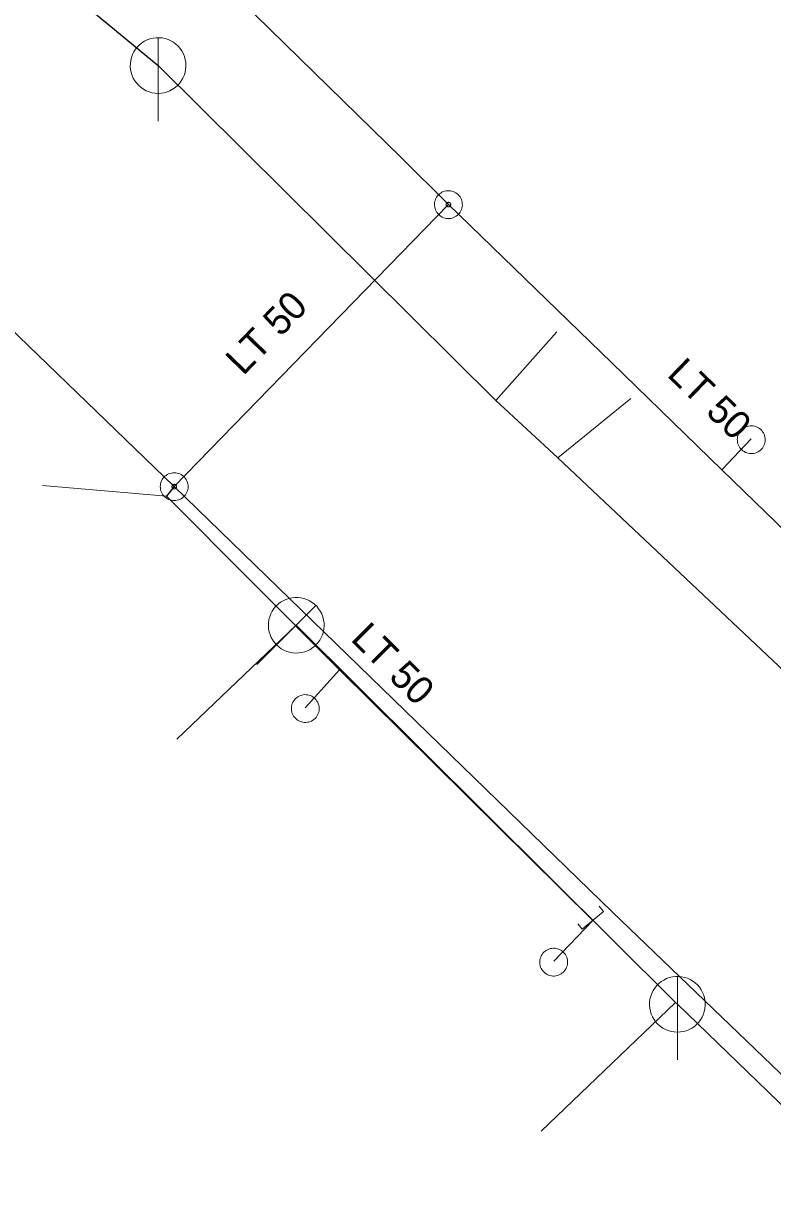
# Model space of a CAD drawing. Extents: x -807203 to -805207, y -993656 to -992505.
# Drawn here: x -805985.68 to -805958.79, y -993323.34 to -993281.18 of the extents above; entities that cross this region are included whole.
import ezdxf

# ---------------------------------------------------------------- set-up
doc = ezdxf.new("R2010")
doc.units = 0
doc.header["$LTSCALE"] = 0.4
for name, color, linetype, lineweight in [('1', 7, 'Continuous', 13), ('11', 7, 'Continuous', 13), ('13', 7, 'Continuous', 13), ('14', 7, 'Continuous', 25), ('17', 7, 'Continuous', 25), ('22', 7, 'Continuous', 13), ('23', 7, 'Continuous', 13), ('47', 7, 'Continuous', 13)]:
    doc.layers.add(name, color=color, linetype=linetype, lineweight=lineweight)

msp = doc.modelspace()

# ---------------------------------------------------------------- linework, layer by layer
at = {"layer": '11'}
for p, q in [((-805966.54, -993292.252), (-805968.73, -993294.715)), ((-805963.884, -993294.643), (-805966.495, -993296.778)), ((-805980.176, -993306.88), (-805975.89, -993302.789)), ((-805967.097, -993320.95), (-805962.28, -993316.329)), ((-805962.21, -993316.399), (-805947.879, -993330.26))]:
    msp.add_line(p, q, dxfattribs=at)
msp.add_lwpolyline([(-805975.89, -993302.789), (-805962.28, -993316.329), (-805962.21, -993316.399)], dxfattribs=at)
at = {"layer": '13'}
for p, q in [((-805960.618, -993297.208), (-805959.558, -993296.094)), ((-805980.55, -993298.156), (-805985.005, -993297.765)), ((-805974.333, -993304.386), (-805975.566, -993305.748)), ((-805965.239, -993313.388), (-805966.649, -993314.853))]:
    msp.add_line(p, q, dxfattribs=at)
at = {"layer": '14'}
for points in [[(-806015.82, -993248.39), (-806008.844, -993255.179), (-805995.221, -993268.897), (-805983.297, -993280.672), (-805980.85, -993282.69)], [(-805980.85, -993282.69), (-805968.73, -993294.715), (-805966.495, -993296.778), (-805953.969, -993308.596), (-805943.489, -993317.82)]]:
    msp.add_lwpolyline(points, dxfattribs=at)
at = {"layer": '17'}
msp.add_line((-805970.428, -993287.685), (-805980.27, -993297.811), dxfattribs=at)
for points in [[(-805970.428, -993287.685), (-805972.109, -993286.008), (-805978.403, -993279.84), (-805988.86, -993269.541), (-805996.668, -993261.975), (-806000.375, -993258.351), (-806005.914, -993252.87), (-806019.053, -993241.45)], [(-805980.27, -993297.811), (-805996.344, -993282.298), (-806025.237, -993255.101)], [(-805970.428, -993287.685), (-805964.557, -993293.37), (-805960.618, -993297.208), (-805957.092, -993300.616), (-805952.748, -993305.003)], [(-805980.27, -993297.811), (-805980.55, -993298.156), (-805974.333, -993304.386), (-805965.239, -993313.388)], [(-805980.27, -993297.811), (-805964.539, -993313.096), (-805944.059, -993332.754), (-805925.796, -993349.072), (-805905.688, -993366.883), (-805894.556, -993375.978), (-805881.298, -993386.71), (-805877.651, -993389.561), (-805871.269, -993394.798), (-805850.666, -993411.467), (-805839.3, -993421.037), (-805830.275, -993428.564)]]:
    msp.add_lwpolyline(points, dxfattribs=at)
at = {"layer": '22'}
for p, q in [((-805980.85, -993284.69), (-805980.849, -993281.69)), ((-805977.306, -993304.201), (-805975.182, -993302.083)), ((-805962.21, -993318.399), (-805962.209, -993315.399))]:
    msp.add_line(p, q, dxfattribs=at)
for points in [[(-805979.85, -993282.69), (-805979.855, -993282.581), (-805979.873, -993282.473), (-805979.903, -993282.367), (-805979.943, -993282.266), (-805979.995, -993282.169), (-805980.057, -993282.079), (-805980.129, -993281.996), (-805980.209, -993281.922), (-805980.297, -993281.856), (-805980.391, -993281.801), (-805980.491, -993281.756), (-805980.596, -993281.723), (-805980.703, -993281.701), (-805980.812, -993281.691), (-805980.922, -993281.693), (-805981.03, -993281.707), (-805981.137, -993281.732), (-805981.24, -993281.769), (-805981.338, -993281.818), (-805981.43, -993281.876), (-805981.516, -993281.945), (-805981.593, -993282.022), (-805981.662, -993282.108), (-805981.721, -993282.2), (-805981.769, -993282.298), (-805981.806, -993282.401), (-805981.832, -993282.508), (-805981.846, -993282.616), (-805981.849, -993282.726), (-805981.839, -993282.835), (-805981.818, -993282.942), (-805981.784, -993283.046), (-805981.74, -993283.146), (-805981.685, -993283.241), (-805981.619, -993283.329), (-805981.545, -993283.409), (-805981.462, -993283.481), (-805981.372, -993283.543), (-805981.276, -993283.595), (-805981.174, -993283.636), (-805981.069, -993283.666), (-805980.961, -993283.684), (-805980.851, -993283.69), (-805980.742, -993283.684), (-805980.634, -993283.666), (-805980.529, -993283.637), (-805980.427, -993283.596), (-805980.33, -993283.544), (-805980.24, -993283.482), (-805980.157, -993283.411), (-805980.082, -993283.331), (-805980.017, -993283.243), (-805979.961, -993283.149), (-805979.917, -993283.049), (-805979.883, -993282.945), (-805979.861, -993282.837), (-805979.851, -993282.728)], [(-805975.184, -993303.497), (-805975.111, -993303.416), (-805975.047, -993303.327), (-805974.993, -993303.23), (-805974.95, -993303.131), (-805974.918, -993303.025), (-805974.898, -993302.918), (-805974.89, -993302.808), (-805974.894, -993302.7), (-805974.91, -993302.591), (-805974.937, -993302.485), (-805974.976, -993302.383), (-805975.027, -993302.285), (-805975.087, -993302.194), (-805975.156, -993302.109), (-805975.236, -993302.033), (-805975.322, -993301.966), (-805975.415, -993301.908), (-805975.514, -993301.862), (-805975.618, -993301.827), (-805975.724, -993301.803), (-805975.833, -993301.79), (-805975.942, -993301.79), (-805976.052, -993301.802), (-805976.159, -993301.825), (-805976.262, -993301.861), (-805976.361, -993301.907), (-805976.455, -993301.964), (-805976.542, -993302.031), (-805976.621, -993302.107), (-805976.691, -993302.191), (-805976.752, -993302.282), (-805976.802, -993302.379), (-805976.841, -993302.481), (-805976.87, -993302.587), (-805976.885, -993302.696), (-805976.89, -993302.805), (-805976.882, -993302.914), (-805976.862, -993303.022), (-805976.831, -993303.126), (-805976.788, -993303.228), (-805976.735, -993303.323), (-805976.672, -993303.412), (-805976.599, -993303.494), (-805976.517, -993303.567), (-805976.428, -993303.631), (-805976.334, -993303.685), (-805976.233, -993303.728), (-805976.127, -993303.76), (-805976.02, -993303.78), (-805975.911, -993303.789), (-805975.801, -993303.785), (-805975.693, -993303.769), (-805975.587, -993303.742), (-805975.485, -993303.703), (-805975.387, -993303.654), (-805975.295, -993303.593), (-805975.211, -993303.523)], [(-805961.21, -993316.399), (-805961.215, -993316.29), (-805961.233, -993316.182), (-805961.263, -993316.076), (-805961.303, -993315.975), (-805961.355, -993315.878), (-805961.417, -993315.788), (-805961.489, -993315.705), (-805961.569, -993315.631), (-805961.657, -993315.565), (-805961.751, -993315.51), (-805961.851, -993315.465), (-805961.956, -993315.432), (-805962.063, -993315.41), (-805962.172, -993315.4), (-805962.282, -993315.402), (-805962.39, -993315.416), (-805962.497, -993315.441), (-805962.6, -993315.478), (-805962.698, -993315.527), (-805962.79, -993315.585), (-805962.876, -993315.654), (-805962.953, -993315.731), (-805963.022, -993315.817), (-805963.081, -993315.909), (-805963.129, -993316.007), (-805963.166, -993316.11), (-805963.192, -993316.217), (-805963.206, -993316.325), (-805963.209, -993316.435), (-805963.199, -993316.544), (-805963.178, -993316.651), (-805963.144, -993316.755), (-805963.1, -993316.855), (-805963.045, -993316.95), (-805962.979, -993317.038), (-805962.905, -993317.118), (-805962.822, -993317.19), (-805962.732, -993317.252), (-805962.636, -993317.304), (-805962.534, -993317.345), (-805962.429, -993317.375), (-805962.321, -993317.393), (-805962.211, -993317.399), (-805962.102, -993317.393), (-805961.994, -993317.375), (-805961.889, -993317.346), (-805961.787, -993317.305), (-805961.69, -993317.253), (-805961.6, -993317.191), (-805961.517, -993317.12), (-805961.442, -993317.04), (-805961.377, -993316.952), (-805961.321, -993316.858), (-805961.277, -993316.758), (-805961.243, -993316.654), (-805961.221, -993316.546), (-805961.211, -993316.437)]]:
    msp.add_lwpolyline(points, close=True, dxfattribs=at)
at = {"layer": '23'}
for points in [[(-805959.216, -993295.76), (-805959.256, -993295.726), (-805959.3, -993295.696), (-805959.346, -993295.673), (-805959.395, -993295.653), (-805959.445, -993295.639), (-805959.497, -993295.63), (-805959.549, -993295.627), (-805959.601, -993295.629), (-805959.653, -993295.636), (-805959.703, -993295.648), (-805959.753, -993295.666), (-805959.801, -993295.69), (-805959.844, -993295.717), (-805959.885, -993295.749), (-805959.923, -993295.785), (-805959.957, -993295.827), (-805959.986, -993295.868), (-805960.011, -993295.916), (-805960.03, -993295.963), (-805960.045, -993296.013), (-805960.053, -993296.067), (-805960.057, -993296.118), (-805960.055, -993296.171), (-805960.048, -993296.223), (-805960.035, -993296.273), (-805960.016, -993296.322), (-805959.994, -993296.369), (-805959.966, -993296.413), (-805959.933, -993296.454), (-805959.897, -993296.492), (-805959.858, -993296.526), (-805959.814, -993296.555), (-805959.767, -993296.58), (-805959.719, -993296.599), (-805959.669, -993296.612), (-805959.618, -993296.622), (-805959.565, -993296.626), (-805959.512, -993296.624), (-805959.461, -993296.616)], [(-805960.011, -993295.916), (-805960.03, -993295.963), (-805960.045, -993296.013), (-805960.053, -993296.067), (-805960.057, -993296.118), (-805960.055, -993296.171), (-805960.048, -993296.223), (-805960.035, -993296.273), (-805960.016, -993296.322), (-805959.994, -993296.369), (-805959.966, -993296.413), (-805959.933, -993296.454), (-805959.897, -993296.492), (-805959.858, -993296.526), (-805959.814, -993296.555), (-805959.767, -993296.58), (-805959.719, -993296.599), (-805959.669, -993296.612), (-805959.618, -993296.622), (-805959.565, -993296.626), (-805959.512, -993296.624), (-805959.461, -993296.616), (-805959.411, -993296.604), (-805959.361, -993296.586), (-805959.314, -993296.564), (-805959.27, -993296.534), (-805959.229, -993296.502), (-805959.191, -993296.467), (-805959.158, -993296.426), (-805959.128, -993296.383), (-805959.103, -993296.336), (-805959.085, -993296.288), (-805959.07, -993296.237), (-805959.06, -993296.187), (-805959.058, -993296.134), (-805959.059, -993296.082), (-805959.066, -993296.031), (-805959.079, -993295.979), (-805959.097, -993295.93), (-805959.12, -993295.883)], [(-805959.461, -993296.616), (-805959.411, -993296.604), (-805959.361, -993296.586), (-805959.314, -993296.564), (-805959.27, -993296.534), (-805959.229, -993296.502), (-805959.191, -993296.467), (-805959.158, -993296.426), (-805959.128, -993296.383), (-805959.103, -993296.336), (-805959.085, -993296.288), (-805959.07, -993296.237), (-805959.06, -993296.187), (-805959.058, -993296.134), (-805959.059, -993296.082), (-805959.066, -993296.031), (-805959.079, -993295.979), (-805959.097, -993295.93), (-805959.12, -993295.883), (-805959.149, -993295.839), (-805959.18, -993295.798), (-805959.216, -993295.76), (-805959.256, -993295.726), (-805959.3, -993295.696), (-805959.346, -993295.673), (-805959.395, -993295.653), (-805959.445, -993295.639), (-805959.497, -993295.63), (-805959.549, -993295.627), (-805959.601, -993295.629), (-805959.653, -993295.636), (-805959.703, -993295.648), (-805959.753, -993295.666), (-805959.801, -993295.69), (-805959.844, -993295.717), (-805959.885, -993295.749), (-805959.923, -993295.785), (-805959.957, -993295.827), (-805959.986, -993295.868), (-805960.011, -993295.916)], [(-805959.12, -993295.883), (-805959.149, -993295.839), (-805959.18, -993295.798), (-805959.216, -993295.76)], [(-805975.21, -993305.429), (-805975.249, -993305.393), (-805975.291, -993305.362), (-805975.336, -993305.337), (-805975.384, -993305.315), (-805975.433, -993305.298), (-805975.485, -993305.288), (-805975.536, -993305.282), (-805975.588, -993305.281), (-805975.64, -993305.286), (-805975.692, -993305.296), (-805975.742, -993305.312), (-805975.791, -993305.333), (-805975.836, -993305.359), (-805975.877, -993305.389), (-805975.917, -993305.423), (-805975.953, -993305.463), (-805975.983, -993305.504), (-805976.01, -993305.55), (-805976.032, -993305.596), (-805976.049, -993305.646), (-805976.059, -993305.699), (-805976.065, -993305.75), (-805976.066, -993305.803), (-805976.062, -993305.855), (-805976.051, -993305.905), (-805976.034, -993305.956), (-805976.014, -993306.003), (-805975.988, -993306.049), (-805975.956, -993306.091), (-805975.923, -993306.131), (-805975.884, -993306.166), (-805975.842, -993306.197), (-805975.796, -993306.224), (-805975.749, -993306.246), (-805975.7, -993306.261), (-805975.649, -993306.272), (-805975.597, -993306.279), (-805975.544, -993306.279), (-805975.492, -993306.274)], [(-805976.01, -993305.55), (-805976.032, -993305.596), (-805976.049, -993305.646), (-805976.059, -993305.699), (-805976.065, -993305.75), (-805976.066, -993305.803), (-805976.062, -993305.855), (-805976.051, -993305.905), (-805976.034, -993305.956), (-805976.014, -993306.003), (-805975.988, -993306.049), (-805975.956, -993306.091), (-805975.923, -993306.131), (-805975.884, -993306.166), (-805975.842, -993306.197), (-805975.796, -993306.224), (-805975.749, -993306.246), (-805975.7, -993306.261), (-805975.649, -993306.272), (-805975.597, -993306.279), (-805975.544, -993306.279), (-805975.492, -993306.274), (-805975.441, -993306.264), (-805975.391, -993306.248), (-805975.343, -993306.228), (-805975.297, -993306.201), (-805975.256, -993306.17), (-805975.216, -993306.136), (-805975.181, -993306.098), (-805975.15, -993306.056), (-805975.123, -993306.01), (-805975.102, -993305.963), (-805975.085, -993305.913), (-805975.073, -993305.863), (-805975.068, -993305.81), (-805975.067, -993305.758), (-805975.072, -993305.706), (-805975.082, -993305.654), (-805975.098, -993305.604), (-805975.119, -993305.556)], [(-805975.492, -993306.274), (-805975.441, -993306.264), (-805975.391, -993306.248), (-805975.343, -993306.228), (-805975.297, -993306.201), (-805975.256, -993306.17), (-805975.216, -993306.136), (-805975.181, -993306.098), (-805975.15, -993306.056), (-805975.123, -993306.01), (-805975.102, -993305.963), (-805975.085, -993305.913), (-805975.073, -993305.863), (-805975.068, -993305.81), (-805975.067, -993305.758), (-805975.072, -993305.706), (-805975.082, -993305.654), (-805975.098, -993305.604), (-805975.119, -993305.556), (-805975.146, -993305.511), (-805975.176, -993305.469), (-805975.21, -993305.429), (-805975.249, -993305.393), (-805975.291, -993305.362), (-805975.336, -993305.337), (-805975.384, -993305.315), (-805975.433, -993305.298), (-805975.485, -993305.288), (-805975.536, -993305.282), (-805975.588, -993305.281), (-805975.64, -993305.286), (-805975.692, -993305.296), (-805975.742, -993305.312), (-805975.791, -993305.333), (-805975.836, -993305.359), (-805975.877, -993305.389), (-805975.917, -993305.423), (-805975.953, -993305.463), (-805975.983, -993305.504), (-805976.01, -993305.55)], [(-805975.119, -993305.556), (-805975.146, -993305.511), (-805975.176, -993305.469), (-805975.21, -993305.429)], [(-805966.293, -993314.534), (-805966.332, -993314.498), (-805966.374, -993314.467), (-805966.419, -993314.442), (-805966.467, -993314.42), (-805966.516, -993314.403), (-805966.568, -993314.393), (-805966.619, -993314.387), (-805966.671, -993314.386), (-805966.723, -993314.391), (-805966.775, -993314.401), (-805966.825, -993314.417), (-805966.874, -993314.438), (-805966.919, -993314.464), (-805966.96, -993314.494), (-805967, -993314.528), (-805967.036, -993314.568), (-805967.066, -993314.609), (-805967.093, -993314.655), (-805967.115, -993314.701), (-805967.132, -993314.751), (-805967.142, -993314.804), (-805967.148, -993314.855), (-805967.149, -993314.908), (-805967.145, -993314.96), (-805967.134, -993315.01), (-805967.117, -993315.061), (-805967.097, -993315.108), (-805967.071, -993315.154), (-805967.039, -993315.196), (-805967.006, -993315.236), (-805966.967, -993315.271), (-805966.925, -993315.302), (-805966.879, -993315.329), (-805966.832, -993315.351), (-805966.783, -993315.366), (-805966.732, -993315.377), (-805966.68, -993315.384), (-805966.627, -993315.384), (-805966.575, -993315.379)], [(-805966.575, -993315.379), (-805966.524, -993315.369), (-805966.474, -993315.353), (-805966.426, -993315.333), (-805966.38, -993315.306), (-805966.339, -993315.275), (-805966.299, -993315.241), (-805966.264, -993315.203), (-805966.233, -993315.161), (-805966.206, -993315.115), (-805966.185, -993315.068), (-805966.168, -993315.018), (-805966.156, -993314.968), (-805966.151, -993314.915), (-805966.15, -993314.863), (-805966.155, -993314.811), (-805966.165, -993314.759), (-805966.181, -993314.709), (-805966.202, -993314.661), (-805966.229, -993314.616), (-805966.259, -993314.574), (-805966.293, -993314.534), (-805966.332, -993314.498), (-805966.374, -993314.467), (-805966.419, -993314.442), (-805966.467, -993314.42), (-805966.516, -993314.403), (-805966.568, -993314.393), (-805966.619, -993314.387), (-805966.671, -993314.386), (-805966.723, -993314.391), (-805966.775, -993314.401), (-805966.825, -993314.417), (-805966.874, -993314.438), (-805966.919, -993314.464), (-805966.96, -993314.494), (-805967, -993314.528), (-805967.036, -993314.568), (-805967.066, -993314.609), (-805967.093, -993314.655)], [(-805967.093, -993314.655), (-805967.115, -993314.701), (-805967.132, -993314.751), (-805967.142, -993314.804), (-805967.148, -993314.855), (-805967.149, -993314.908), (-805967.145, -993314.96), (-805967.134, -993315.01), (-805967.117, -993315.061), (-805967.097, -993315.108), (-805967.071, -993315.154), (-805967.039, -993315.196), (-805967.006, -993315.236), (-805966.967, -993315.271), (-805966.925, -993315.302), (-805966.879, -993315.329), (-805966.832, -993315.351), (-805966.783, -993315.366), (-805966.732, -993315.377), (-805966.68, -993315.384), (-805966.627, -993315.384), (-805966.575, -993315.379), (-805966.524, -993315.369), (-805966.474, -993315.353), (-805966.426, -993315.333), (-805966.38, -993315.306), (-805966.339, -993315.275), (-805966.299, -993315.241), (-805966.264, -993315.203), (-805966.233, -993315.161), (-805966.206, -993315.115), (-805966.185, -993315.068), (-805966.168, -993315.018), (-805966.156, -993314.968), (-805966.151, -993314.915), (-805966.15, -993314.863), (-805966.155, -993314.811), (-805966.165, -993314.759), (-805966.181, -993314.709), (-805966.202, -993314.661)], [(-805966.202, -993314.661), (-805966.229, -993314.616), (-805966.259, -993314.574), (-805966.293, -993314.534)]]:
    msp.add_lwpolyline(points, dxfattribs=at)
at = {"layer": '47'}
for points in [[(-805970.079, -993287.326), (-805970.118, -993287.292), (-805970.161, -993287.261), (-805970.207, -993287.237), (-805970.255, -993287.215), (-805970.305, -993287.2), (-805970.357, -993287.19), (-805970.408, -993287.186), (-805970.461, -993287.186), (-805970.512, -993287.192), (-805970.564, -993287.203), (-805970.614, -993287.22), (-805970.661, -993287.243), (-805970.706, -993287.269), (-805970.748, -993287.301), (-805970.786, -993287.336), (-805970.82, -993287.375), (-805970.851, -993287.418), (-805970.876, -993287.465), (-805970.897, -993287.512), (-805970.912, -993287.562), (-805970.922, -993287.614), (-805970.927, -993287.666), (-805970.926, -993287.718), (-805970.921, -993287.77), (-805970.909, -993287.821), (-805970.892, -993287.871), (-805970.87, -993287.919), (-805970.843, -993287.963), (-805970.811, -993288.005), (-805970.776, -993288.043), (-805970.737, -993288.077), (-805970.694, -993288.108), (-805970.648, -993288.134), (-805970.6, -993288.154), (-805970.55, -993288.169), (-805970.499, -993288.18), (-805970.447, -993288.185), (-805970.394, -993288.184), (-805970.342, -993288.178), (-805970.291, -993288.166), (-805970.241, -993288.149), (-805970.194, -993288.127), (-805970.149, -993288.1), (-805970.107, -993288.068), (-805970.069, -993288.033), (-805970.035, -993287.994), (-805970.004, -993287.951), (-805969.979, -993287.906), (-805969.958, -993287.857), (-805969.943, -993287.807), (-805969.932, -993287.756), (-805969.928, -993287.704), (-805969.929, -993287.652), (-805969.935, -993287.6), (-805969.946, -993287.548), (-805969.963, -993287.498), (-805969.985, -993287.452), (-805970.012, -993287.406), (-805970.044, -993287.364)], [(-805970.37, -993287.626), (-805970.377, -993287.619), (-805970.384, -993287.615), (-805970.391, -993287.611), (-805970.399, -993287.608), (-805970.407, -993287.605), (-805970.416, -993287.604), (-805970.424, -993287.602), (-805970.433, -993287.603), (-805970.441, -993287.604), (-805970.45, -993287.606), (-805970.458, -993287.609), (-805970.466, -993287.612), (-805970.473, -993287.617), (-805970.48, -993287.621), (-805970.486, -993287.627), (-805970.493, -993287.634), (-805970.497, -993287.641), (-805970.501, -993287.648), (-805970.504, -993287.656), (-805970.507, -993287.664), (-805970.508, -993287.673), (-805970.51, -993287.681), (-805970.509, -993287.69), (-805970.509, -993287.699), (-805970.506, -993287.707), (-805970.503, -993287.715), (-805970.5, -993287.723), (-805970.495, -993287.73), (-805970.491, -993287.737), (-805970.485, -993287.743), (-805970.478, -993287.75), (-805970.471, -993287.754), (-805970.464, -993287.758), (-805970.456, -993287.761), (-805970.448, -993287.764), (-805970.44, -993287.766), (-805970.431, -993287.767), (-805970.422, -993287.766), (-805970.413, -993287.766), (-805970.405, -993287.763), (-805970.397, -993287.76), (-805970.389, -993287.757), (-805970.382, -993287.752), (-805970.375, -993287.748), (-805970.369, -993287.742), (-805970.362, -993287.735), (-805970.358, -993287.728), (-805970.354, -993287.721), (-805970.351, -993287.713), (-805970.348, -993287.705), (-805970.346, -993287.697), (-805970.345, -993287.688), (-805970.346, -993287.679), (-805970.347, -993287.671), (-805970.349, -993287.662), (-805970.352, -993287.654), (-805970.355, -993287.646), (-805970.36, -993287.639), (-805970.364, -993287.632)], [(-805979.77, -993297.811), (-805979.773, -993297.759), (-805979.781, -993297.706), (-805979.795, -993297.657), (-805979.813, -993297.608), (-805979.837, -993297.561), (-805979.866, -993297.517), (-805979.899, -993297.477), (-805979.936, -993297.44), (-805979.976, -993297.407), (-805980.02, -993297.378), (-805980.067, -993297.353), (-805980.116, -993297.336), (-805980.166, -993297.322), (-805980.218, -993297.314), (-805980.27, -993297.311), (-805980.322, -993297.314), (-805980.374, -993297.322), (-805980.425, -993297.336), (-805980.473, -993297.353), (-805980.52, -993297.378), (-805980.564, -993297.407), (-805980.605, -993297.44), (-805980.642, -993297.477), (-805980.675, -993297.517), (-805980.703, -993297.561), (-805980.727, -993297.608), (-805980.746, -993297.657), (-805980.759, -993297.706), (-805980.767, -993297.759), (-805980.77, -993297.811), (-805980.767, -993297.863), (-805980.759, -993297.915), (-805980.746, -993297.966), (-805980.727, -993298.014), (-805980.703, -993298.061), (-805980.675, -993298.105), (-805980.642, -993298.146), (-805980.605, -993298.183), (-805980.564, -993298.216), (-805980.52, -993298.244), (-805980.473, -993298.268), (-805980.425, -993298.287), (-805980.374, -993298.299), (-805980.322, -993298.308), (-805980.27, -993298.311), (-805980.218, -993298.308), (-805980.166, -993298.299), (-805980.116, -993298.287), (-805980.067, -993298.268), (-805980.02, -993298.244), (-805979.976, -993298.216), (-805979.936, -993298.183), (-805979.899, -993298.146), (-805979.866, -993298.105), (-805979.837, -993298.061), (-805979.813, -993298.014), (-805979.795, -993297.966), (-805979.781, -993297.915), (-805979.773, -993297.863)], [(-805980.188, -993297.811), (-805980.188, -993297.802), (-805980.19, -993297.794), (-805980.192, -993297.786), (-805980.195, -993297.777), (-805980.199, -993297.77), (-805980.204, -993297.763), (-805980.209, -993297.755), (-805980.215, -993297.75), (-805980.222, -993297.745), (-805980.229, -993297.74), (-805980.237, -993297.736), (-805980.245, -993297.733), (-805980.253, -993297.731), (-805980.261, -993297.728), (-805980.27, -993297.728), (-805980.279, -993297.728), (-805980.287, -993297.731), (-805980.295, -993297.733), (-805980.303, -993297.736), (-805980.311, -993297.74), (-805980.318, -993297.745), (-805980.325, -993297.75), (-805980.331, -993297.755), (-805980.337, -993297.763), (-805980.341, -993297.77), (-805980.345, -993297.777), (-805980.348, -993297.786), (-805980.35, -993297.794), (-805980.352, -993297.802), (-805980.352, -993297.811), (-805980.352, -993297.82), (-805980.35, -993297.828), (-805980.348, -993297.836), (-805980.345, -993297.844), (-805980.341, -993297.852), (-805980.337, -993297.858), (-805980.331, -993297.866), (-805980.325, -993297.872), (-805980.318, -993297.878), (-805980.311, -993297.882), (-805980.303, -993297.886), (-805980.295, -993297.889), (-805980.287, -993297.891), (-805980.279, -993297.893), (-805980.27, -993297.893), (-805980.261, -993297.893), (-805980.253, -993297.891), (-805980.245, -993297.889), (-805980.237, -993297.886), (-805980.229, -993297.882), (-805980.222, -993297.878), (-805980.215, -993297.872), (-805980.209, -993297.866), (-805980.204, -993297.858), (-805980.199, -993297.852), (-805980.195, -993297.844), (-805980.192, -993297.836), (-805980.19, -993297.828), (-805980.188, -993297.82)]]:
    msp.add_lwpolyline(points, close=True, dxfattribs=at)
msp.add_lwpolyline([(-805965.016, -993312.878), (-805964.856, -993313.072), (-805965.621, -993313.703), (-805965.782, -993313.508)], dxfattribs=at)

# ---------------------------------------------------------------- texts
at = {"layer": '1'}
for rotation, p in [(46, (-805977.797, -993293.854)), (316, (-805962.618, -993293.823)), (315, (-805973.971, -993303.31))]:
    msp.add_text('LT 50 ', height=1, rotation=rotation, dxfattribs=at).set_placement(p)

doc.saveas('drawing.dxf')
